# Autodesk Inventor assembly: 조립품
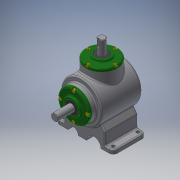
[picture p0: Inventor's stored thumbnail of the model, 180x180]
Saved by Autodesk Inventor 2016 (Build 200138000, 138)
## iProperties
Created: 2018-08
Part Number: 조립품
Material: 일반
Document SubType Name: Assembly
Designer: USER
Author: USER
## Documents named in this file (14)
- C:\Users\USER\Desktop\480807V1022\조립품.iam
- C:\Users\USER\Desktop\480807V1022\본체.ipt
- C:\Users\USER\Desktop\480807V1022\메인 베벨기어.ipt
- C:\Users\USER\Desktop\480807V1022\메인 축.ipt
- 메인 축.ipt
- C:\Users\USER\Desktop\480807V1022\베어링 6203.ipt
- C:\Users\USER\Desktop\480807V1022\볼트 M4.ipt
- C:\Users\USER\Desktop\480807V1022\서브 베벨기어.ipt
- C:\Users\USER\Desktop\480807V1022\서브 축.ipt
- 서브 축.ipt
- C:\Users\USER\Desktop\480807V1022\오일실 17 32 8.ipt
- C:\Users\USER\Desktop\480807V1022\커버.ipt
- C:\Users\USER\Desktop\480807V1022\키 4x4.ipt
- C:\Users\USER\Desktop\480807V1022\키 5x5.ipt
